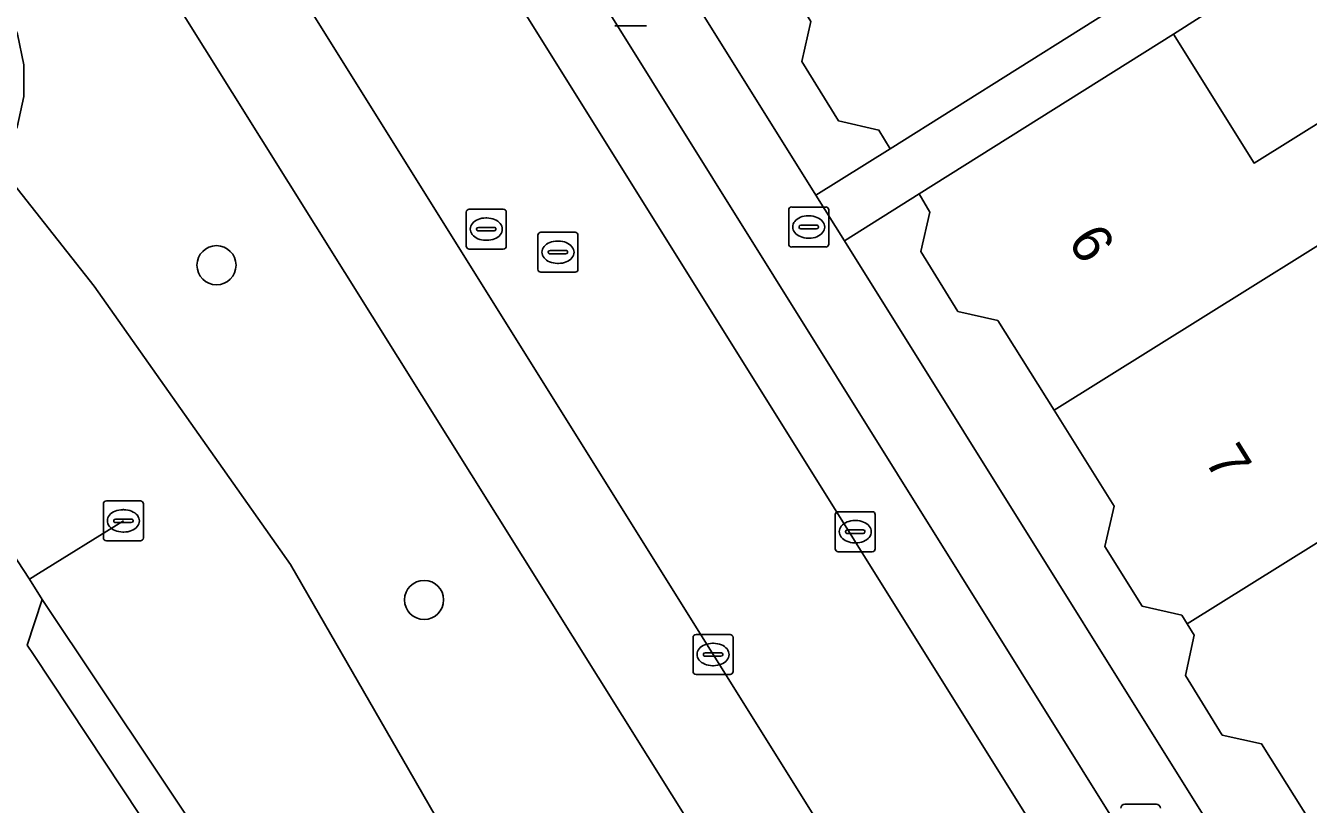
# Model space of a CAD drawing. Extents: x 159664 to 160323, y 385312 to 386115.
# Drawn here: x 159927.2 to 159959.3, y 385991.46 to 386010.94 of the extents above; entities that cross this region are included whole.
import ezdxf

# ---------------------------------------------------------------- set-up
doc = ezdxf.new("R2010")
doc.units = 0
for name, color, linetype in [('IMGEO_Boom', 7, 'Continuous'), ('IMGEO_Brandkraan', 7, 'Continuous'), ('IMGEO_Duiker', 7, 'Continuous'), ('IMGEO_Erf', 7, 'Continuous'), ('IMGEO_Groenvoorziening', 7, 'Continuous'), ('IMGEO_Kolk', 7, 'Continuous'), ('IMGEO_Lichtmast', 7, 'Continuous'), ('IMGEO_Meer_plas_ven_vijver', 7, 'Continuous'), ('IMGEO_Oever', 7, 'Continuous'), ('IMGEO_Pand', 7, 'Continuous'), ('IMGEO_Pand_nummerreeks', 7, 'Continuous'), ('IMGEO_Parkeervlak_open', 7, 'Continuous'), ('IMGEO_Rijbaan_lokaal_open', 7, 'Continuous'), ('IMGEO_Rioolput', 7, 'Continuous'), ('IMGEO_Voetpad_open', 7, 'Continuous')]:
    doc.layers.add(name, color=color, linetype=linetype)

msp = doc.modelspace()

# ---------------------------------------------------------------- linework, layer by layer
at = {"layer": 'IMGEO_Boom'}
for centre in [(159931.972, 386004.946), (159937.168, 385996.573)]:
    msp.add_circle(centre, 0.489, dxfattribs=at)
at = {"layer": 'IMGEO_Brandkraan'}
for p, q in [((159946.291, 386005.476), (159946.291, 386006.328)), ((159946.366, 386006.402), (159947.218, 386006.402)), ((159947.292, 386006.328), (159947.292, 386005.476)), ((159946.55, 386005.896), (159946.55, 386005.908)), ((159946.593, 386005.945), (159946.991, 386005.945)), ((159946.779, 386006.182), (159946.804, 386006.182)), ((159947.034, 386005.908), (159947.034, 386005.896)), ((159946.988, 386005.859), (159946.59, 386005.859)), ((159946.802, 386005.622), (159946.777, 386005.622)), ((159947.218, 386005.402), (159946.366, 386005.402))]:
    msp.add_line(p, q, dxfattribs=at)
for points in [[(159946.291, 386005.476), (159946.291, 386006.328)], [(159946.366, 386006.402), (159947.218, 386006.402)], [(159947.292, 386006.328), (159947.292, 386005.476)], [(159947.218, 386005.402), (159946.366, 386005.402)]]:
    msp.add_lwpolyline(points, dxfattribs=at)
for centre, radius, start, end in [((159946.368, 386006.326), 0.0765, 91.552, 178.448), ((159946.368, 386006.326), 0.0765, 91.552, 178.448), ((159947.216, 386006.326), 0.0765, 1.552, 88.448), ((159947.216, 386006.326), 0.0765, 1.552, 88.448), ((159946.59, 386005.905), 0.0403, 85.8775, 175.7526), ((159946.587, 386005.895), 0.0366, 178.938, 274.7102), ((159946.991, 386005.902), 0.043, 264.8664, 352.4533), ((159946.995, 386005.907), 0.0386, 1.7309, 96.639), ((159946.368, 386005.478), 0.0765, 181.552, 268.448), ((159946.368, 386005.478), 0.0765, 181.552, 268.448), ((159947.216, 386005.478), 0.0765, 271.552, 358.448), ((159947.216, 386005.478), 0.0765, 271.552, 358.448)]:
    msp.add_arc(centre, radius, start, end, dxfattribs=at)
for centre, major_axis, ratio, start_param, end_param in [((159946.778, 386005.902), (-0.387, 0.002), 0.722429, 4.712389, 7.853982), ((159946.803, 386005.902), (-0.39, 0.002), 0.717154, 1.570796, 4.712389)]:
    msp.add_ellipse(centre, major_axis=major_axis, ratio=ratio, start_param=start_param, end_param=end_param, dxfattribs=at)
at = {"layer": 'IMGEO_Duiker'}
msp.add_lwpolyline([(159929.642, 385998.551), (159927.522, 385997.238), (159927.289, 385997.094)], dxfattribs=at)
at = {"layer": 'IMGEO_Erf'}
for points in [[(159927.976, 386037.096), (159946.972, 386006.7), (159948.83, 386007.861), (159948.549, 386008.326), (159947.541, 386008.556), (159946.616, 386010.041), (159946.849, 386011.045), (159945.393, 386013.39), (159943.948, 386015.714), (159942.944, 386015.931), (159942.014, 386017.42), (159942.223, 386018.408), (159942.016, 386018.757), (159941.918, 386018.918), (159940.946, 386019.132), (159940.01, 386020.621), (159940.236, 386021.621), (159938.725, 386024.043), (159937.62, 386025.809), (159936.426, 386026.073), (159934.676, 386028.873), (159932.199, 386032.828), (159933.429, 386033.597), (159932.181, 386035.593)], [(159972.471, 386021.286), (159955.923, 386010.723), (159957.939, 386007.502), (159962.821, 386010.541)], [(159959.575, 385990.666), (159958.126, 385992.973), (159957.143, 385993.192), (159956.22, 385994.679), (159956.439, 385995.695), (159956.266, 385995.972), (159956.127, 385996.189), (159955.134, 385996.42), (159954.201, 385997.911), (159954.439, 385998.919), (159952.935, 386001.32), (159951.525, 386003.566), (159950.528, 386003.789), (159949.594, 386005.29), (159949.821, 386006.275), (159949.555, 386006.728), (159947.685, 386005.559), (159971.661, 385967.195)]]:
    msp.add_lwpolyline(points, dxfattribs=at)
at = {"layer": 'IMGEO_Groenvoorziening'}
for points in [[(159955.282, 385972.677), (159935.869, 386003.671), (159924.707, 386021.493), (159923.616, 386016.481), (159926.674, 386011.449), (159926.994, 386010.725), (159927.155, 386009.956), (159927.153, 386009.17), (159926.987, 386008.402), (159926.418, 386007.571), (159928.912, 386004.426), (159932.034, 386000), (159933.824, 385997.462), (159936.786, 385992.325), (159938.156, 385989.949)], [(159933.013, 385964.523), (159936.698, 385970.64), (159934.473, 385972.702), (159938.586, 385980.338), (159936.875, 385988.981), (159938.156, 385989.949), (159936.786, 385992.325), (159933.824, 385997.462), (159932.034, 386000), (159928.912, 386004.426), (159926.418, 386007.571), (159923.381, 386003.14), (159925.432, 386000), (159926.995, 385997.554), (159927.289, 385997.094), (159927.613, 385996.586), (159933.368, 385987.972), (159935.993, 385983.951)]]:
    msp.add_lwpolyline(points, dxfattribs=at)
at = {"layer": 'IMGEO_Kolk'}
for p, q in [((159947.456, 385997.854), (159947.456, 385998.706)), ((159947.531, 385998.78), (159948.383, 385998.78)), ((159947.944, 385998.56), (159947.969, 385998.56)), ((159948.457, 385998.706), (159948.457, 385997.854)), ((159947.715, 385998.274), (159947.715, 385998.286)), ((159948.153, 385998.237), (159947.755, 385998.237)), ((159947.758, 385998.323), (159948.156, 385998.323)), ((159948.199, 385998.286), (159948.199, 385998.274)), ((159947.967, 385998), (159947.942, 385998)), ((159948.383, 385997.78), (159947.531, 385997.78)), ((159943.898, 385994.782), (159943.898, 385995.634)), ((159943.973, 385995.708), (159944.825, 385995.708)), ((159944.899, 385995.634), (159944.899, 385994.782)), ((159944.386, 385995.488), (159944.411, 385995.488)), ((159944.157, 385995.202), (159944.157, 385995.214)), ((159944.595, 385995.165), (159944.197, 385995.165)), ((159944.2, 385995.251), (159944.598, 385995.251)), ((159944.641, 385995.214), (159944.641, 385995.202)), ((159944.825, 385994.708), (159943.973, 385994.708)), ((159944.409, 385994.928), (159944.384, 385994.928))]:
    msp.add_line(p, q, dxfattribs=at)
for points in [[(159947.456, 385997.854), (159947.456, 385998.706)], [(159947.531, 385998.78), (159948.383, 385998.78)], [(159948.457, 385998.706), (159948.457, 385997.854)], [(159948.383, 385997.78), (159947.531, 385997.78)], [(159943.898, 385994.782), (159943.898, 385995.634)], [(159943.973, 385995.708), (159944.825, 385995.708)], [(159944.899, 385995.634), (159944.899, 385994.782)], [(159944.825, 385994.708), (159943.973, 385994.708)]]:
    msp.add_lwpolyline(points, dxfattribs=at)
for centre, radius, start, end in [((159947.533, 385998.704), 0.0765, 91.552, 178.448), ((159947.533, 385998.704), 0.0765, 91.552, 178.448), ((159948.381, 385998.704), 0.0765, 1.552, 88.448), ((159948.381, 385998.704), 0.0765, 1.552, 88.448), ((159947.755, 385998.283), 0.0403, 85.8775, 175.7526), ((159947.752, 385998.273), 0.0366, 178.938, 274.7102), ((159948.156, 385998.28), 0.043, 264.8664, 352.4533), ((159948.16, 385998.285), 0.0386, 1.7309, 96.639), ((159947.533, 385997.856), 0.0765, 181.552, 268.448), ((159947.533, 385997.856), 0.0765, 181.552, 268.448), ((159948.381, 385997.856), 0.0765, 271.552, 358.448), ((159948.381, 385997.856), 0.0765, 271.552, 358.448), ((159943.975, 385995.632), 0.0765, 91.552, 178.448), ((159943.975, 385995.632), 0.0765, 91.552, 178.448), ((159944.823, 385995.632), 0.0765, 1.552, 88.448), ((159944.823, 385995.632), 0.0765, 1.552, 88.448), ((159944.197, 385995.211), 0.0403, 85.8775, 175.7526), ((159944.194, 385995.201), 0.0366, 178.938, 274.7102), ((159944.598, 385995.208), 0.043, 264.8664, 352.4533), ((159944.602, 385995.213), 0.0386, 1.7309, 96.639), ((159943.975, 385994.784), 0.0765, 181.552, 268.448), ((159943.975, 385994.784), 0.0765, 181.552, 268.448), ((159944.823, 385994.784), 0.0765, 271.552, 358.448), ((159944.823, 385994.784), 0.0765, 271.552, 358.448)]:
    msp.add_arc(centre, radius, start, end, dxfattribs=at)
for centre, major_axis, ratio, start_param, end_param in [((159947.943, 385998.28), (-0.387, 0.002), 0.722429, 4.712389, 7.853982), ((159947.968, 385998.28), (-0.39, 0.002), 0.717154, 1.570796, 4.712389), ((159944.385, 385995.208), (-0.387, 0.002), 0.722429, 4.712389, 7.853982), ((159944.41, 385995.208), (-0.39, 0.002), 0.717154, 1.570796, 4.712389)]:
    msp.add_ellipse(centre, major_axis=major_axis, ratio=ratio, start_param=start_param, end_param=end_param, dxfattribs=at)
at = {"layer": 'IMGEO_Lichtmast'}
for p, q in [((159942.729, 386010.938), (159941.939, 386010.938)), ((159941.939, 386010.938), (159942.729, 386010.938)), ((159954.702, 385991.46), (159955.492, 385991.46)), ((159955.492, 385991.46), (159954.702, 385991.46))]:
    msp.add_line(p, q, dxfattribs=at)
for centre, start, end in [((159954.702, 385991.36), 90, 180), ((159954.702, 385991.36), 90, 180), ((159955.492, 385991.36), 0, 90), ((159955.492, 385991.36), 360, 90)]:
    msp.add_arc(centre, 0.1, start, end, dxfattribs=at)
at = {"layer": 'IMGEO_Meer_plas_ven_vijver'}
msp.add_lwpolyline([(159934.957, 385983.792), (159927.397, 385995.208), (159927.238, 385995.439), (159927.613, 385996.586), (159927.289, 385997.094), (159926.995, 385997.554), (159925.848, 385997.683), (159925.68, 385997.954), (159924.344, 386000), (159921.27, 386004.71)], dxfattribs=at)
at = {"layer": 'IMGEO_Oever'}
msp.add_lwpolyline([(159935.993, 385983.951), (159933.368, 385987.972), (159927.613, 385996.586), (159927.238, 385995.439), (159927.397, 385995.208), (159934.957, 385983.792)], dxfattribs=at)
at = {"layer": 'IMGEO_Pand'}
for points in [[(159953.175, 386015.113), (159958.054, 386018.161), (159956.645, 386020.41), (159945.393, 386013.39), (159946.849, 386011.045), (159946.616, 386010.041), (159947.541, 386008.556), (159948.549, 386008.326), (159948.83, 386007.861), (159955.207, 386011.867)], [(159964.19, 386008.341), (159962.821, 386010.541), (159957.939, 386007.502), (159955.923, 386010.723), (159949.555, 386006.728), (159949.821, 386006.275), (159949.594, 386005.29), (159950.528, 386003.789), (159951.525, 386003.566), (159952.935, 386001.32)], [(159960.757, 386003.023), (159965.62, 386006.043), (159965.316, 386006.532), (159964.362, 386008.064), (159964.19, 386008.341), (159952.935, 386001.32), (159954.439, 385998.919), (159954.201, 385997.911), (159955.134, 385996.42), (159956.127, 385996.189), (159956.266, 385995.972), (159962.667, 385999.966)], [(159970.826, 385997.685), (159969.452, 385999.916), (159964.576, 385996.912), (159962.667, 385999.966), (159956.266, 385995.972), (159956.439, 385995.695), (159956.22, 385994.679), (159957.143, 385993.192), (159958.126, 385992.973), (159959.575, 385990.666)]]:
    msp.add_lwpolyline(points, close=True, dxfattribs=at)
at = {"layer": 'IMGEO_Parkeervlak_open'}
for points in [[(159925.856, 386033.371), (159959.016, 385980.344)], [(160007.649, 385905.881), (159928.962, 386031.821)]]:
    msp.add_lwpolyline(points, dxfattribs=at)
at = {"layer": 'IMGEO_Rijbaan_lokaal_open'}
msp.add_lwpolyline([(159959.016, 385980.344), (159925.856, 386033.371), (159924.811, 386035.12), (159920.972, 386032.678), (159955.159, 385977.993)], close=True, dxfattribs=at)
at = {"layer": 'IMGEO_Rioolput'}
for p, q in [((159938.223, 386005.423), (159938.223, 386006.275)), ((159938.298, 386006.349), (159939.15, 386006.349)), ((159939.224, 386006.275), (159939.224, 386005.423)), ((159938.525, 386005.892), (159938.923, 386005.892)), ((159938.711, 386006.129), (159938.736, 386006.129)), ((159938.482, 386005.843), (159938.482, 386005.855)), ((159938.92, 386005.806), (159938.522, 386005.806)), ((159938.734, 386005.569), (159938.709, 386005.569)), ((159938.966, 386005.855), (159938.966, 386005.843)), ((159940.017, 386004.845), (159940.017, 386005.697)), ((159940.092, 386005.771), (159940.944, 386005.771)), ((159941.018, 386005.697), (159941.018, 386004.845)), ((159939.15, 386005.349), (159938.298, 386005.349)), ((159940.276, 386005.265), (159940.276, 386005.277)), ((159940.319, 386005.314), (159940.717, 386005.314)), ((159940.505, 386005.551), (159940.53, 386005.551)), ((159940.76, 386005.277), (159940.76, 386005.265)), ((159940.714, 386005.228), (159940.316, 386005.228)), ((159940.528, 386004.991), (159940.503, 386004.991)), ((159940.944, 386004.771), (159940.092, 386004.771)), ((159929.141, 385998.125), (159929.141, 385998.977)), ((159929.216, 385999.051), (159930.068, 385999.051)), ((159929.629, 385998.831), (159929.654, 385998.831)), ((159930.142, 385998.977), (159930.142, 385998.125)), ((159929.4, 385998.545), (159929.4, 385998.557)), ((159929.838, 385998.508), (159929.44, 385998.508)), ((159929.443, 385998.594), (159929.841, 385998.594)), ((159929.884, 385998.557), (159929.884, 385998.545)), ((159929.652, 385998.271), (159929.627, 385998.271)), ((159930.068, 385998.051), (159929.216, 385998.051))]:
    msp.add_line(p, q, dxfattribs=at)
for points in [[(159938.223, 386005.423), (159938.223, 386006.275)], [(159938.298, 386006.349), (159939.15, 386006.349)], [(159939.224, 386006.275), (159939.224, 386005.423)], [(159940.017, 386004.845), (159940.017, 386005.697)], [(159940.092, 386005.771), (159940.944, 386005.771)], [(159941.018, 386005.697), (159941.018, 386004.845)], [(159939.15, 386005.349), (159938.298, 386005.349)], [(159940.944, 386004.771), (159940.092, 386004.771)], [(159929.141, 385998.125), (159929.141, 385998.977)], [(159929.216, 385999.051), (159930.068, 385999.051)], [(159930.142, 385998.977), (159930.142, 385998.125)], [(159930.068, 385998.051), (159929.216, 385998.051)]]:
    msp.add_lwpolyline(points, dxfattribs=at)
for centre, radius, start, end in [((159938.3, 386006.273), 0.0765, 91.552, 178.448), ((159938.3, 386006.273), 0.0765, 91.552, 178.448), ((159939.148, 386006.273), 0.0765, 1.552, 88.448), ((159939.148, 386006.273), 0.0765, 1.552, 88.448), ((159938.522, 386005.852), 0.0403, 85.8775, 175.7526), ((159938.927, 386005.854), 0.0386, 1.7309, 96.639), ((159938.519, 386005.842), 0.0366, 178.938, 274.7102), ((159938.923, 386005.849), 0.043, 264.8664, 352.4533), ((159940.094, 386005.695), 0.0765, 91.552, 178.448), ((159940.094, 386005.695), 0.0765, 91.552, 178.448), ((159940.942, 386005.695), 0.0765, 1.552, 88.448), ((159940.942, 386005.695), 0.0765, 1.552, 88.448), ((159938.3, 386005.425), 0.0765, 181.552, 268.448), ((159938.3, 386005.425), 0.0765, 181.552, 268.448), ((159939.148, 386005.425), 0.0765, 271.552, 358.448), ((159939.148, 386005.425), 0.0765, 271.552, 358.448), ((159940.316, 386005.274), 0.0403, 85.8775, 175.7526), ((159940.313, 386005.264), 0.0366, 178.938, 274.7102), ((159940.717, 386005.271), 0.043, 264.8664, 352.4533), ((159940.721, 386005.276), 0.0386, 1.7309, 96.639), ((159940.094, 386004.847), 0.0765, 181.552, 268.448), ((159940.094, 386004.847), 0.0765, 181.552, 268.448), ((159940.942, 386004.847), 0.0765, 271.552, 358.448), ((159940.942, 386004.847), 0.0765, 271.552, 358.448), ((159929.218, 385998.975), 0.0765, 91.552, 178.448), ((159929.218, 385998.975), 0.0765, 91.552, 178.448), ((159930.066, 385998.975), 0.0765, 1.552, 88.448), ((159930.066, 385998.975), 0.0765, 1.552, 88.448), ((159929.44, 385998.554), 0.0403, 85.8775, 175.7526), ((159929.437, 385998.544), 0.0366, 178.938, 274.7102), ((159929.841, 385998.551), 0.043, 264.8664, 352.4533), ((159929.845, 385998.556), 0.0386, 1.7309, 96.639), ((159929.218, 385998.127), 0.0765, 181.552, 268.448), ((159929.218, 385998.127), 0.0765, 181.552, 268.448), ((159930.066, 385998.127), 0.0765, 271.552, 358.448), ((159930.066, 385998.127), 0.0765, 271.552, 358.448)]:
    msp.add_arc(centre, radius, start, end, dxfattribs=at)
for centre, major_axis, ratio, start_param, end_param in [((159938.71, 386005.849), (-0.387, 0.002), 0.722429, 4.712389, 7.853982), ((159938.735, 386005.849), (-0.39, 0.002), 0.717154, 1.570796, 4.712389), ((159940.504, 386005.271), (-0.387, 0.002), 0.722429, 4.712389, 7.853982), ((159940.529, 386005.271), (-0.39, 0.002), 0.717154, 1.570796, 4.712389), ((159929.628, 385998.551), (-0.387, 0.002), 0.722429, 4.712389, 7.853982), ((159929.653, 385998.551), (-0.39, 0.002), 0.717154, 1.570796, 4.712389)]:
    msp.add_ellipse(centre, major_axis=major_axis, ratio=ratio, start_param=start_param, end_param=end_param, dxfattribs=at)
at = {"layer": 'IMGEO_Voetpad_open'}
for points in [[(160035.946, 385864.298), (160011.524, 385903.327), (160009.458, 385906.629), (159986.636, 385943.101), (159975.855, 385960.448), (159975.052, 385961.74), (159971.661, 385967.195), (159947.685, 386005.559), (159946.972, 386006.7), (159927.976, 386037.096), (159924.811, 386035.12), (159925.856, 386033.371)], [(159920.972, 386032.678), (159918.634, 386031.189), (159922.172, 386025.541), (159924.707, 386021.493), (159935.869, 386003.671), (159955.282, 385972.677), (159957.008, 385971.838)], [(159956.151, 385976.381), (159955.159, 385977.993), (159920.972, 386032.678)], [(159928.962, 386031.821), (160007.649, 385905.881), (160007.996, 385906.094), (160010.404, 385902.292), (160010.038, 385902.057), (160043.232, 385848.929)], [(159970.237, 386021.476), (159955.207, 386011.867), (159948.83, 386007.861), (159946.972, 386006.7), (159947.685, 386005.559), (159949.555, 386006.728), (159955.923, 386010.723), (159972.471, 386021.286)]]:
    msp.add_lwpolyline(points, dxfattribs=at)

# ---------------------------------------------------------------- texts
at = {"layer": 'IMGEO_Pand_nummerreeks'}
for s, p in [('6', (159953.259, 386005.552)), ('7', (159956.679, 386000.067))]:
    msp.add_text(s, height=1, rotation=301.9365, dxfattribs=at).set_placement(p)

doc.saveas('drawing.dxf')
